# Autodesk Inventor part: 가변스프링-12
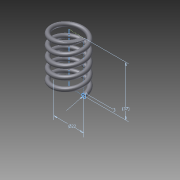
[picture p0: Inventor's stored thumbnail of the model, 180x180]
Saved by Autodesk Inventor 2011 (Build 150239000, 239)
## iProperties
Created: 2015-05
Part Number: 가변스프링-12
Material: 탄소강
Document SubType Name: Modeling
Designer: Administrator
Mass: 19.2243 g
Surface Area: 32.8046 cm^2
Volume: 2.44273 cm^3
Density: 7.87 g/cm^3
Author: Administrator
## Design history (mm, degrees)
sketch "스케치1"
  geometry: L1 (0, 0)-(-11, 0); L2 (-11, 0)-(-11, 36.411); L3 (-11, 36.411)-(0, 36.411); L4 (0, 36.411)-(0, 0); C1 r 1.5 at (-11, 0)
  constraints: 8 end point, 2 parallel, 1 centre point, 1 coincident, 1 horizontal, 1 perpendicular
  dimensions: "d0" = 3 diameter of C1; "d1" = 22 diameter of L2 L4; "d2" = 36.4112 distance of L1.end L2.end (derived)
feature "코일1" sketch "스케치1" pitch "d3" = 10; turns "d5" = 5; dims "d4" = 36.4112 (= d2), "d6" = 0, angle "d7" = 90 deg, angle "d8" = 90 deg, "d9" = 0, "d10" = 0
node "작업 평면1"
sketch "스케치2"
  geometry: L1 (3, 0)-(0, 0) reference; 1 further point
  constraints: 1 horizontal alignment
extrude "돌출1" cut sketch "스케치2" distance "d11" = 10; taper "d12" = 0 deg
node "작업 평면2"
sketch "스케치3"
  geometry: L1 (0, 0)-(3, 0) reference; 1 further point
  constraints: 1 horizontal alignment
extrude "돌출2" cut sketch "스케치3" distance "d13" = 10; taper "d14" = 0 deg
node "솔리드1"
node "절단 모서리 투영1"
node "절단 모서리 투영2"
